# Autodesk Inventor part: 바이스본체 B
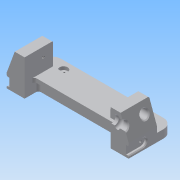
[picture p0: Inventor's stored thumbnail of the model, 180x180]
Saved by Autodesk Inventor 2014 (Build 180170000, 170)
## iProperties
Created: 2017-04
Part Number: 바이스본체 B
Material: 알루미늄 6061
Document SubType Name: Modeling
Designer: mduedu
Density: 2.71 g/cm^3
Mass: 324.158 g
Surface Area: 275.767 cm^2
Volume: 119.615 cm^3
Appearance: 기본값
Author: mduedu
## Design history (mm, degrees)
sketch "스케치1"
  geometry: L1 (-75, 0)-(75, 0); L2 (-75, 0)-(-75, 17); L3 (-53, 17)-(53, 17); L4 (75, 17)-(75, 0); L5 (-75, 17)-(-65.173, 44); L6 (-65.173, 44)-(-53, 44); L7 (-53, 44)-(-53, 17); L8 (0, 0)-(0, 17); L9 (75, 17)-(65.173, 44); L10 (65.173, 44)-(53, 44); L11 (53, 44)-(53, 17); 1 further point
  constraints: 22 end point, 4 perpendicular, 2 horizontal alignment, 2 midpoint, 2 symmetric about line, 1 coincident, 1 collinear, 1 horizontal, 1 vertical
  dimensions: "d0" = 150 distance of L1.start L1.end; "d1" = 17 distance of L1.start L2.end; "d2" = 27 distance of L3.start L6.end; "d3" = 22 distance of L3.start L2.end; "d4" = 70 deg angle of L3 L5; "d54" = 20 deg angle of L9 L4
extrude "돌출1" new body sketch "스케치1" stored distance "d5" = 70; taper "d6" = 0 deg
sketch "스케치2"
  geometry: L1 (0, 70)-(106, 70) reference; L2 (106, 70)-(106, 0) reference; L3 (106, 0)-(0, 0) reference; L4 (0, 47)-(106, 47); L5 (106, 47)-(106, 23); L6 (106, 23)-(0, 23); L7 (0, 23)-(0, 47); L8 (0, 70)-(0, 0) reference; 2 further points
  constraints: 8 end point, 2 parallel, 2 point on line, 1 horizontal, 1 horizontal alignment, 1 midpoint, 1 perpendicular
  dimensions: "d7" = 24 distance between parallel lines of L6 L4
extrude "돌출2" cut sketch "스케치2" stored distance "d9" = 70; taper "d10" = 0 deg
sketch "스케치3"
  geometry: L1 (22, -23)-(128, -23) reference; L2 (128, -47)-(22, -47) reference; L3 (22, -18)-(128, -18); L4 (128, -52)-(22, -52); L5 (22, -18)-(22, -52); L6 (128, -18)-(128, -52); 1 further point
  constraints: 8 end point, 3 parallel, 2 point on line, 1 perpendicular
  dimensions: "d11" = 5 distance between parallel lines of L3 L1; "d12" = 5 distance between parallel lines of L4 L2
extrude "돌출3" cut sketch "스케치3" distance "d13" = 12; taper "d14" = 0 deg
fillet "모깎기1" dims "d15" = 3, "d16" = 3
sketch "스케치4"
  geometry: L1 (103, 23)-(3, 23) reference; L2 (0, 26)-(0, 0) reference; L3 (106, 0)-(0, 0) reference; L4 (106, 26)-(106, 0) reference; L5 (96, 0)-(90, 0); L6 (90, 0)-(90, 19.5); L7 (96, 19.5)-(96, 0); L8 (90, 19.5)-(96, 19.5); A1 r 3 centre (3, 26) between (0, 26) and (3, 23) reference; A2 r 3 centre (103, 26) between (103, 23) and (106, 26) reference; 1 further point
  constraints: 8 end point, 2 perpendicular, 1 horizontal, 1 parallel, 1 point on line
  dimensions: "d17" = 10 distance between parallel lines of L7 L4; "d18" = 6 distance between parallel lines of L7 L6; "d27" = 3.5 distance between parallel lines of L8 L1
extrude "돌출4" join sketch "스케치4" distance "d19" = 12; taper "d20" = 0 deg
chamfer "모따기1" distance "d21" = 3; stored, may be unused: second distance "d22" = 2, angle "d23" = 45 deg
chamfer "모따기2" distance "d24" = 3; stored, may be unused: second distance "d25" = 2, angle "d26" = 45 deg
sketch "스케치5"
  geometry: L1 (-15.5, 35.8)-(-15.5, -25.8) reference; L2 (19.5, 0)-(0, 0) reference; C1 r 6.5 at (9.5, 15); 1 further point
  constraints: 1 centre point
  dimensions: "d28" = 13 diameter of C1; "d30" = 15 distance from line of C1.centre L2; "d31" = 25 distance from line of C1.centre L1
extrude "돌출5" cut sketch "스케치5" stored distance "d32" = 12; taper "d33" = 0 deg
sketch "스케치6"
  geometry: C1 r 5 at (-10, 15); C2 r 5 at (-60, 15); A1 r 6.5 centre (-10, 15) between (-15.766, 12) and (-4.234, 12) reference; A2 r 6.5 centre (-60, 15) between (-65.766, 12) and (-54.234, 12) reference; 1 further point
  constraints: 2 centre point, 2 coincident
  dimensions: "d34" = 10 diameter of C1; "d35" = 10 diameter of C2 (= d34)
extrude "돌출6" cut sketch "스케치6" stored distance "d36" = 12; taper "d37" = 0 deg
chamfer "모따기3" distance "d38" = 1; stored, may be unused: second distance "d39" = 2, angle "d40" = 45 deg
chamfer "모따기4" distance "d41" = 1; stored, may be unused: second distance "d42" = 2, angle "d43" = 45 deg
sketch "스케치7"
  geometry: L1 (-35, 35.8)-(-35, -25.8) reference; L2 (-70, 0)-(0, 0) reference; C1 r 5 at (-35, 15); 1 further point
  constraints: 1 centre point, 1 point on line
  dimensions: "d44" = 10 diameter of C1; "d45" = 15 distance from line of C1.centre L2
extrude "돌출7" cut sketch "스케치7" stored distance "d46" = 12; taper "d47" = 0 deg
chamfer "모따기5" distance "d48" = 1; stored, may be unused: second distance "d49" = 2, angle "d50" = 45 deg
node "작업축1"
sketch "스케치8"
  geometry: L1 (-105, 32)-(105, 32) reference; L2 (58, 32)-(64, 32); L3 (64, 32)-(64, 40); L4 (64, 40)-(58, 40); L5 (58, 40)-(58, 32); L6 (53, 38)-(53, 26) reference; 1 further point
  constraints: 8 end point, 2 parallel, 1 horizontal, 1 perpendicular, 1 point on line
  dimensions: "d51" = 5 distance from line of L6 L2.start; "d52" = 6 distance of L3.end L4.end; "d53" = 16 diameter of L4 L1
revolve "회전1" sketch "스케치8" stored, may be unused: angle "d55" = 90 deg
fillet "모깎기2"
chamfer "모따기6" distance "d56" = 1; stored, may be unused: second distance "d57" = 2, angle "d58" = 45 deg
sketch "스케치9"
  geometry: L1 (17.5, 3)-(52.5, 3); L2 (52.5, 13)-(17.5, 13); L3 (70, 0)-(0, 0) reference; L4 (17.5, 8)-(52.5, 8); A1 r 5 centre (17.5, 8) between (17.5, 13) and (17.5, 3); A2 r 5 centre (52.5, 8) between (52.5, 3) and (52.5, 13); 3 further points
  constraints: 6 end point, 4 point on circle, 3 tangent, 2 centre point, 2 midpoint, 2 parallel, 1 horizontal, 1 vertical alignment
  dimensions: "d59" = 35 distance of L4.start L4.end; "d61" = 5 radius of A2; "d62" = 8 distance between parallel lines of L3 L4
extrude "돌출8" cut sketch "스케치9" distance "d63" = 3; taper "d64" = 0 deg
chamfer "모따기7" distance "d65" = 1; stored, may be unused: second distance "d66" = 2, angle "d67" = 45 deg
chamfer "모따기8" distance "d68" = 1; stored, may be unused: second distance "d69" = 2, angle "d70" = 45 deg
feature "분할1"
sketch "스케치10"
  geometry: A1 r 5 centre (0, 0) between (0, 5) and (0, -5) reference; 1 further point
  constraints: 1 coincident
hole "구멍1" sketch "스케치10" at (0, 0) diameter "d71" = 2.459; stored, may be unused: countersink angle "d75" = 90 deg, drill point angle "d77" = 120 deg; dims "d72" = 4.5, "d73" = 4, "d74" = 2, "d76" = 6
sketch "스케치11"
  geometry: L1 (0, 0)-(0, 27) reference; L2 (0, 27)-(-35, 27) reference; 2 further points
  dimensions: "d78" = 12 distance from line of point (-12, 15.5) L1; "d79" = 11.5 distance from line of point (-12, 15.5) L2
hole "구멍2" sketch "스케치11" at (-12, 15.5) diameter "d80" = 3.242; stored, may be unused: countersink angle "d84" = 90 deg, drill point angle "d86" = 120 deg; dims "d81" = 6, "d82" = 4, "d83" = 2, "d85" = 8
sketch "스케치12"
  geometry: L1 (-75, -35)-(-75, 0) reference; L2 (75, -35)-(75, 0) reference; L3 (75, -35)-(-75, -35); L4 (-75, -35)-(-75, -55); L5 (-75, -55)-(75, -55); L6 (75, -55)-(75, -35); 1 further point
  constraints: 8 end point, 2 parallel, 1 horizontal, 1 perpendicular, 1 point on line
  dimensions: "d87" = 20 distance of L3.end L4.end; "d89" = 150 distance of L4.end L5.end (derived)
extrude "돌출9" join sketch "스케치12" distance "d90" = 10; taper "d91" = 0 deg
sketch "스케치13"
  geometry: L1 (-75, 55)-(-75, 35) reference; L2 (75, 35)-(75, 55) reference; L3 (-75, 45)-(75, 45); 3 further points
  constraints: 2 end point, 2 midpoint, 2 point on line
  dimensions: "d92" = 50 horizontal distance of point (-50, 45) point (0, 0); "d93" = 100 distance of point (50, 45) point (-50, 45)
fillet "모깎기3" dims "d94" = 12
chamfer "모따기9" distance "d95" = 1; stored, may be unused: second distance "d96" = 2, angle "d97" = 45 deg
hole "구멍3" sketch "스케치13" diameter "d98" = 4.134; stored, may be unused: countersink angle "d102" = 90 deg, drill point angle "d104" = 118 deg; dims "d99" = 6, "d100" = 10, "d101" = 4, "d103" = 8
node "솔리드1"
mirror "대칭1"
mirror "대칭2"
mirror "대칭3"
mirror "대칭4"
node "투영된 루프1"
